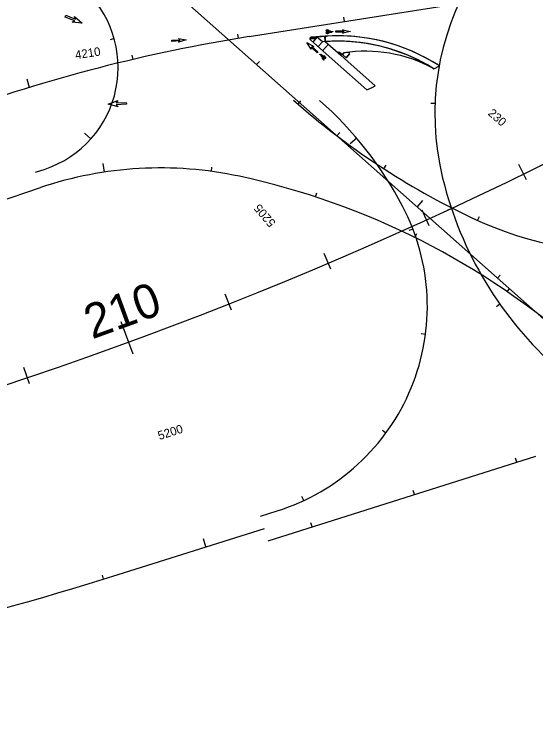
# Model space of a CAD drawing. Extents: x -5665 to 1997148, y 4 to 827579.
# Drawn here: x 1971224 to 1971710, y 802183 to 802844 of the extents above; entities that cross this region are included whole.
import ezdxf

# ---------------------------------------------------------------- set-up
doc = ezdxf.new("R2010")
doc.units = 0
for name, color, linetype in [('RD_HC_CL_Rel', 7, 'Continuous'), ('RD_HC_Data_Tic_Rel', 7, 'Continuous'), ('RD_HC_TX_Rel_Sta50', 7, 'Continuous'), ('RD_PD_SW', 7, 'Continuous'), ('RD_Sketch8', 7, 'Continuous')]:
    doc.layers.add(name, color=color, linetype=linetype)

msp = doc.modelspace()

# ---------------------------------------------------------------- linework, layer by layer
at = {"layer": 'RD_HC_CL_Rel'}
for p, q in [((1970807.31, 803367.72), (1971858, 802435.06)), ((1971443.3, 802823.09), (1971690.74, 802862.31)), ((1971244.1, 802696.62), (1971253.1, 802699.65)), ((1970599.21, 802463.58), (1971248.89, 802682.4)), ((1971460.99, 802353.28), (1971710.27, 802431.95)), ((1971453.77, 802376.17), (1971469.44, 802381.11)), ((1971321.29, 802321.77), (1971457.38, 802364.72))]:
    msp.add_line(p, q, dxfattribs=at)
for centre, radius, start, end in [((1971866.23, 802750.94), 250, 104.64509, 193.79732), ((1971221.18, 802794.42), 100, 288.61459, 48.40581), ((1971678.18, 801341.59), 1500, 99.00871, 109.98385), ((1971949.12, 803287.5), 700, 228.40581, 244.77603), ((1971276.54, 802501.92), 350, 27.78301, 48.40581), ((1970020.89, 806126.39), 3819.72, 269.57213, 296.64085), ((1971360.61, 802350.71), 350, 77.87082, 108.61459), ((1971287.07, 802008.53), 700, 48.40581, 77.87082), ((1971963.34, 802774.78), 350, 193.79732, 228.40581), ((1971799.96, 802970.88), 350, 244.77603, 302.28244), ((1971409.25, 802571.84), 200, 287.51539, 27.78301), ((1970418.4, 805182.68), 3000, 269.57213, 287.51539)]:
    msp.add_arc(centre, radius, start, end, dxfattribs=at)
at = {"layer": 'RD_HC_Data_Tic_Rel'}
for p, q in [((1971532, 802837.15), (1971531.38, 802841.1)), ((1971317.5, 802821.29), (1971313.65, 802820.21)), ((1971433.24, 802821.46), (1971432.59, 802825.4)), ((1971335.2, 802801.85), (1971334.29, 802805.75)), ((1971450.17, 802797.07), (1971452.83, 802800.06)), ((1971238.68, 802775.76), (1971236.34, 802783.41)), ((1971488.8, 802760.14), (1971491.43, 802763.16)), ((1971616.42, 802760.76), (1971612.42, 802760.92)), ((1971295.84, 802727.88), (1971289.86, 802733.21)), ((1971524.96, 802730.68), (1971527.62, 802733.68)), ((1971543.41, 802728.37), (1971537.31, 802723.2)), ((1971308.39, 802696.8), (1971307.2, 802704.71)), ((1971568.57, 802699.98), (1971570.74, 802703.34)), ((1971701.47, 802689.57), (1971694.44, 802703.94)), ((1971408.05, 802697.48), (1971408.59, 802701.45)), ((1971505.06, 802673.72), (1971506.3, 802677.52)), ((1971599.75, 802664.3), (1971605.06, 802670.28)), ((1971631.82, 802662.55), (1971628.04, 802661.27)), ((1971610.92, 802646.75), (1971604.28, 802661.3)), ((1971656.1, 802651.81), (1971657.74, 802655.45)), ((1971595.88, 802643.73), (1971592.14, 802642.3)), ((1971597.54, 802635.91), (1971599.32, 802639.49)), ((1971519.29, 802606.32), (1971513.03, 802621.04)), ((1971674.53, 802597.91), (1971677.19, 802600.91)), ((1971426.64, 802568.3), (1971420.76, 802583.18)), ((1971683.7, 802585.31), (1971685.97, 802588.61)), ((1971676.9, 802573.66), (1971673.62, 802571.37)), ((1971335.07, 802527.09), (1971324.1, 802557.15)), ((1971607.5, 802545.46), (1971603.53, 802545.98)), ((1971238.49, 802499.61), (1971233.4, 802514.78)), ((1971570.58, 802453.64), (1971567.35, 802456)), ((1971692.72, 802426.41), (1971691.51, 802430.23)), ((1971597.35, 802396.31), (1971596.15, 802400.13)), ((1971494.16, 802390.76), (1971492.46, 802394.38)), ((1971501.99, 802366.22), (1971500.79, 802370.03)), ((1971403.02, 802347.57), (1971400.61, 802355.2)), ((1971307.64, 802317.5), (1971306.46, 802321.32))]:
    msp.add_line(p, q, dxfattribs=at)
at = {"layer": 'RD_PD_SW'}
for p, q in [((1971501.22, 802822.71), (1971515.3, 802823.55)), ((1971513.89, 802823.46), (1971501.22, 802822.71)), ((1971502.72, 802817.95), (1971506.7, 802822.43)), ((1971511.42, 802818.26), (1971506.07, 802823)), ((1971514.19, 802818.47), (1971513.85, 802823.46)), ((1971514.19, 802818.47), (1971513.89, 802823.46)), ((1971513.89, 802823.46), (1971514.19, 802818.47)), ((1971514.19, 802818.47), (1971513.89, 802823.46)), ((1971500.31, 802820.09), (1971523.26, 802799.72)), ((1971500.31, 802820.09), (1971523.26, 802799.72)), ((1971507.43, 802813.77), (1971511.41, 802818.26)), ((1971517.02, 802815.96), (1971511.71, 802809.97)), ((1971517.22, 802815.78), (1971514.19, 802818.47)), ((1971514.19, 802818.47), (1971528.57, 802805.7)), ((1971514.19, 802818.47), (1971517.22, 802815.78)), ((1971526.19, 802807.81), (1971517.22, 802815.78)), ((1971517.22, 802815.78), (1971526.19, 802807.81)), ((1971531.9, 802818.74), (1971530.24, 802818.79)), ((1971526.19, 802807.81), (1971527.19, 802808.93)), ((1971527.19, 802808.93), (1971530.13, 802806.33)), ((1971531.5, 802807.87), (1971530.13, 802806.33)), ((1971530.13, 802806.33), (1971531.5, 802807.87)), ((1971536.8, 802807.09), (1971536.62, 802808.58)), ((1971528.24, 802805.33), (1971528.29, 802805.29)), ((1971530.13, 802806.33), (1971533.48, 802803.35)), ((1971536.8, 802807.09), (1971533.48, 802803.35)), ((1971533.48, 802803.35), (1971536.8, 802807.09)), ((1971522.93, 802799.35), (1971522.98, 802799.3)), ((1971523.26, 802799.72), (1971552.77, 802773.53)), ((1971523.31, 802799.68), (1971552.77, 802773.53)), ((1971615.26, 802793.14), (1971620.47, 802795.74)), ((1971614.23, 802793.58), (1971614.31, 802793.72))]:
    msp.add_line(p, q, dxfattribs=at)
msp.add_lwpolyline([(1971505.51, 802822.93), (1971500.54, 802822.52), (1971500.67, 802820.93), (1971505.64, 802821.34)], close=True, dxfattribs=at)
for points in [[(1971513.89, 802823.46), (1971513.89, 802823.46)], [(1971560.69, 802777.19), (1971535.17, 802799.85), (1971528.57, 802805.7), (1971526.19, 802807.81)], [(1971614.31, 802793.72), (1971615.26, 802793.14), (1971620.45, 802795.75), (1971619.55, 802796.34)], [(1971552.77, 802773.53), (1971557.72, 802775.82), (1971560.69, 802777.19)]]:
    msp.add_lwpolyline(points, dxfattribs=at)
for centre, radius in [((1971500.87, 802822.25), 0.146), ((1971500.91, 802821.74), 0.146), ((1971500.87, 802822.25), 0.073), ((1971500.95, 802821.25), 0.146), ((1971500.91, 802821.74), 0.073), ((1971500.95, 802821.25), 0.073), ((1971501.27, 802822.28), 0.146), ((1971501.31, 802821.78), 0.146), ((1971501.27, 802822.28), 0.073), ((1971501.35, 802821.28), 0.146), ((1971501.31, 802821.78), 0.073), ((1971501.35, 802821.28), 0.073), ((1971501.67, 802822.32), 0.146), ((1971501.71, 802821.81), 0.146), ((1971501.67, 802822.32), 0.073), ((1971501.75, 802821.31), 0.146), ((1971501.71, 802821.81), 0.073), ((1971501.75, 802821.31), 0.073), ((1971502.06, 802822.35), 0.146), ((1971502.11, 802821.84), 0.146), ((1971502.06, 802822.35), 0.073), ((1971502.15, 802821.35), 0.146), ((1971502.11, 802821.84), 0.073), ((1971502.15, 802821.35), 0.073), ((1971502.46, 802822.38), 0.146), ((1971502.5, 802821.88), 0.146), ((1971502.46, 802822.38), 0.073), ((1971502.55, 802821.38), 0.146), ((1971502.5, 802821.88), 0.073), ((1971502.55, 802821.38), 0.073), ((1971502.86, 802822.42), 0.146), ((1971502.9, 802821.91), 0.146), ((1971502.86, 802822.42), 0.073), ((1971502.94, 802821.41), 0.146), ((1971502.9, 802821.91), 0.073), ((1971502.94, 802821.41), 0.073), ((1971503.26, 802822.45), 0.146), ((1971503.3, 802821.94), 0.146), ((1971503.26, 802822.45), 0.073), ((1971503.34, 802821.44), 0.146), ((1971503.3, 802821.94), 0.073), ((1971503.34, 802821.44), 0.073), ((1971503.66, 802822.48), 0.146), ((1971503.7, 802821.97), 0.146), ((1971503.66, 802822.48), 0.073), ((1971503.74, 802821.48), 0.146), ((1971503.7, 802821.97), 0.073), ((1971503.74, 802821.48), 0.073), ((1971504.06, 802822.51), 0.146), ((1971504.1, 802822.01), 0.146), ((1971504.06, 802822.51), 0.073), ((1971504.14, 802821.51), 0.146), ((1971504.1, 802822.01), 0.073), ((1971504.14, 802821.51), 0.073), ((1971504.46, 802822.55), 0.146), ((1971504.5, 802822.04), 0.146), ((1971504.46, 802822.55), 0.073), ((1971504.54, 802821.54), 0.146), ((1971504.5, 802822.04), 0.073), ((1971504.54, 802821.54), 0.073), ((1971504.86, 802822.58), 0.146), ((1971504.9, 802822.07), 0.146), ((1971504.86, 802822.58), 0.073), ((1971504.94, 802821.58), 0.146), ((1971504.9, 802822.07), 0.073), ((1971504.94, 802821.58), 0.073), ((1971505.25, 802822.61), 0.146), ((1971505.3, 802822.11), 0.146), ((1971505.25, 802822.61), 0.073), ((1971505.34, 802821.61), 0.146), ((1971505.3, 802822.11), 0.073), ((1971505.34, 802821.61), 0.073)]:
    msp.add_circle(centre, radius, dxfattribs=at)
for centre, radius, start, end in [((1971501.31, 802821.21), 1.5, 93.40581, 228.40581), ((1971501.31, 802821.21), 1.5, 93.40581, 228.40581), ((1971525.64, 802649.86), 174, 56.97514, 95.44839), ((1971525.64, 802649.86), 174, 57.33665, 93.87004), ((1971525.63, 802649.82), 169.04, 57.9779, 94.8263), ((1971525.64, 802649.86), 169, 58.35128, 93.88378), ((1971525.64, 802649.86), 169, 88.43947, 93.88378), ((1971525.64, 802649.86), 169, 58.35128, 87.87679), ((1971551.92, 802679.49), 130, 61.36, 99.03754), ((1971551.92, 802679.49), 130, 96.75765, 99.03754)]:
    msp.add_arc(centre, radius, start, end, dxfattribs=at)
at = {"layer": 'RD_Sketch8'}
for p, q in [((1971271.8, 802841.31), (1971272.49, 802842.98)), ((1971280.69, 802837.67), (1971271.8, 802841.31)), ((1971272.49, 802842.98), (1971281.37, 802839.33)), ((1971280.59, 802841.86), (1971287.8, 802835.72)), ((1971281.37, 802839.33), (1971280.59, 802841.86)), ((1971278.36, 802836.42), (1971280.69, 802837.67)), ((1971287.8, 802835.72), (1971278.36, 802836.42)), ((1971516, 802828.23), (1971516.01, 802828.47)), ((1971516.01, 802828.47), (1971516.01, 802828.23)), ((1971516.01, 802828.23), (1971516.01, 802828.47)), ((1971516.05, 802829.4), (1971516.04, 802829.16)), ((1971516.04, 802829.16), (1971516.05, 802829.4)), ((1971523.99, 802828.37), (1971531.67, 802828.38)), ((1971523.99, 802827.33), (1971523.99, 802828.37)), ((1971537.52, 802827.87), (1971530.32, 802826.16)), ((1971530.33, 802829.55), (1971537.52, 802827.87)), ((1971531.67, 802828.38), (1971530.33, 802829.55)), ((1971377.34, 802821.28), (1971384.63, 802820.05)), ((1971378.76, 802820.19), (1971377.34, 802821.28)), ((1971515.9, 802826.07), (1971515.91, 802826.3)), ((1971515.92, 802826.3), (1971515.91, 802826.07)), ((1971515.91, 802826.07), (1971515.92, 802826.3)), ((1971515.95, 802827.23), (1971515.94, 802826.99)), ((1971515.94, 802826.99), (1971515.95, 802827.23)), ((1971531.67, 802827.34), (1971523.99, 802827.33)), ((1971530.32, 802826.16), (1971531.67, 802827.34)), ((1971371.09, 802819.69), (1971378.76, 802820.19)), ((1971371.16, 802818.66), (1971371.09, 802819.69)), ((1971378.82, 802819.16), (1971371.16, 802818.66)), ((1971384.63, 802820.05), (1971377.55, 802817.9)), ((1971377.55, 802817.9), (1971378.82, 802819.16)), ((1971501.08, 802811.45), (1971496.86, 802817.52)), ((1971496.86, 802817.52), (1971503.35, 802813.96)), ((1971506.58, 802808.08), (1971500.87, 802813.22)), ((1971500.87, 802813.22), (1971501.08, 802811.45)), ((1971503.35, 802813.96), (1971501.56, 802813.99)), ((1971501.56, 802813.99), (1971507.27, 802808.85)), ((1971507.27, 802808.85), (1971506.58, 802808.08)), ((1971511.95, 802802.18), (1971511.78, 802802)), ((1971511.79, 802802), (1971511.95, 802802.17)), ((1971512.43, 802802.67), (1971512.6, 802802.84)), ((1971512.6, 802802.84), (1971512.43, 802802.67)), ((1971512.6, 802802.84), (1971512.44, 802802.67)), ((1971513.31, 802803.55), (1971513.48, 802803.72)), ((1971513.48, 802803.72), (1971513.31, 802803.55)), ((1971514.12, 802804.38), (1971513.96, 802804.21)), ((1971513.96, 802804.21), (1971514.12, 802804.38)), ((1971514.12, 802804.38), (1971513.96, 802804.21)), ((1971311.93, 802760.1), (1971320.78, 802763.47)), ((1971320.78, 802763.47), (1971319.2, 802761.35)), ((1971319.2, 802761.35), (1971328.79, 802761.82)), ((1971328.79, 802761.82), (1971328.88, 802760.02)), ((1971321.06, 802757.6), (1971311.93, 802760.1)), ((1971328.88, 802760.02), (1971319.29, 802759.56)), ((1971319.29, 802759.56), (1971321.06, 802757.6))]:
    msp.add_line(p, q, dxfattribs=at)
for points in [[(1971520.29, 802827.39), (1971519.64, 802827.92), (1971518.66, 802828.29), (1971518.32, 802828.14), (1971519.3, 802827.76), (1971518.32, 802827.55), (1971517.99, 802828.15), (1971516.68, 802828.04), (1971516.96, 802827.72), (1971517.64, 802827.75), (1971517.93, 802827.39), (1971515.64, 802828.02), (1971515.34, 802827.75), (1971518.25, 802826.92)], [(1971521.03, 802827.86), (1971521.05, 802827.81), (1971521.06, 802827.77), (1971521.07, 802827.74), (1971521.08, 802827.72), (1971521.08, 802827.69), (1971521.08, 802827.67), (1971521.07, 802827.64), (1971521.06, 802827.61), (1971521.05, 802827.6), (1971521.03, 802827.55), (1971521.01, 802827.53), (1971520.35, 802827.56), (1971520.33, 802827.6), (1971520.32, 802827.63), (1971520.31, 802827.68), (1971520.3, 802827.72), (1971520.31, 802827.77), (1971520.32, 802827.81), (1971520.34, 802827.84), (1971520.35, 802827.87), (1971520.36, 802827.89)], [(1971509.12, 802806.47), (1971509.13, 802806.53), (1971509.15, 802806.57), (1971509.16, 802806.6), (1971509.18, 802806.62), (1971509.2, 802806.64), (1971509.21, 802806.65), (1971509.23, 802806.67), (1971509.26, 802806.68), (1971509.28, 802806.69), (1971509.32, 802806.71), (1971509.35, 802806.71), (1971509.83, 802806.25), (1971509.81, 802806.21), (1971509.8, 802806.17), (1971509.77, 802806.13), (1971509.75, 802806.09), (1971509.71, 802806.07), (1971509.67, 802806.04), (1971509.64, 802806.03), (1971509.61, 802806.02), (1971509.59, 802806.01)], [(1971509.98, 802806.33), (1971510.11, 802805.51), (1971510.59, 802804.57), (1971510.94, 802804.46), (1971510.47, 802805.4), (1971511.34, 802804.9), (1971511.18, 802804.22), (1971512.23, 802803.44), (1971512.23, 802803.86), (1971511.71, 802804.29), (1971511.74, 802804.75), (1971513.01, 802802.76), (1971513.41, 802802.75), (1971511.81, 802805.31)]]:
    msp.add_lwpolyline(points, close=True, dxfattribs=at)
for centre, major_axis, ratio, start_param, end_param in [((1971516.05, 802828.81), (-1.38, 0.06), 0.421657, 0.002013, 1.556277), ((1971516.05, 802828.81), (-1.38, 0.06), 0.421657, 4.73092, 6.285191), ((1971516.02, 802828.81), (-1.05, 0.04), 0.327603, 4.968366, 6.281137), ((1971516.02, 802828.81), (-1.05, 0.04), 0.327603, 6.281144, 7.855553), ((1971516.02, 802828.81), (-1.05, 0.04), 0.327603, 4.706721, 4.968366), ((1971516.02, 802828.81), (-1.05, 0.04), 0.327603, 1.575, 3.139545), ((1971516.05, 802828.81), (-1.38, 0.06), 0.421657, 1.55828, 3.143599), ((1971516.02, 802828.81), (-1.05, 0.04), 0.327603, 3.139551, 4.704089), ((1971516.05, 802828.81), (-1.38, 0.06), 0.421657, 3.205785, 4.728917), ((1971516.05, 802828.81), (-1.38, 0.06), 0.421657, 3.143612, 3.205785), ((1971515.95, 802826.65), (-1.38, 0.06), 0.421657, 0.002013, 1.556277), ((1971515.95, 802826.65), (-1.38, 0.06), 0.421657, 4.73092, 6.285191), ((1971515.92, 802826.65), (-1.05, 0.04), 0.327603, 4.968366, 6.281137), ((1971515.92, 802826.65), (-1.05, 0.04), 0.327603, 6.281144, 7.855553), ((1971515.92, 802826.65), (-1.05, 0.04), 0.327603, 4.706721, 4.968366), ((1971515.95, 802826.65), (-1.38, 0.06), 0.421657, 1.55828, 3.143599), ((1971515.92, 802826.65), (-1.05, 0.04), 0.327603, 1.575, 3.139545), ((1971515.92, 802826.65), (-1.05, 0.04), 0.327603, 3.139551, 4.704089), ((1971515.95, 802826.65), (-1.38, 0.06), 0.421657, 3.205785, 4.728917), ((1971515.95, 802826.65), (-1.38, 0.06), 0.421657, 3.143612, 3.205785), ((1971512.18, 802802.44), (0.984, -0.971), 0.421657, 3.205785, 4.728917), ((1971512.18, 802802.44), (0.984, -0.971), 0.421657, 3.143612, 3.205785), ((1971512.18, 802802.44), (0.984, -0.971), 0.421657, 1.55828, 3.143599), ((1971512.2, 802802.42), (0.757, -0.73), 0.327603, 3.139551, 4.704089), ((1971512.2, 802802.42), (0.757, -0.73), 0.327603, 1.575, 3.139545), ((1971512.18, 802802.44), (0.984, -0.971), 0.421657, 4.73092, 6.285191), ((1971512.2, 802802.42), (0.757, -0.73), 0.327603, 4.706721, 4.968366), ((1971512.2, 802802.42), (0.757, -0.73), 0.327603, 4.968366, 6.281137), ((1971512.2, 802802.42), (0.757, -0.73), 0.327603, 6.281144, 7.855553), ((1971513.7, 802803.98), (0.984, -0.971), 0.421657, 3.205785, 4.728917), ((1971512.18, 802802.44), (0.984, -0.971), 0.421657, 0.002013, 1.556277), ((1971513.7, 802803.98), (0.984, -0.971), 0.421657, 3.143612, 3.205785), ((1971513.7, 802803.98), (0.984, -0.971), 0.421657, 1.55828, 3.143599), ((1971513.72, 802803.96), (0.757, -0.73), 0.327603, 3.139551, 4.704089), ((1971513.72, 802803.96), (0.757, -0.73), 0.327603, 1.575, 3.139545), ((1971513.7, 802803.98), (0.984, -0.971), 0.421657, 4.73092, 6.285191), ((1971513.72, 802803.96), (0.757, -0.73), 0.327603, 4.706721, 4.968366), ((1971513.72, 802803.96), (0.757, -0.73), 0.327603, 4.968366, 6.281137), ((1971513.72, 802803.96), (0.757, -0.73), 0.327603, 6.281144, 7.855553), ((1971513.7, 802803.98), (0.984, -0.971), 0.421657, 0.002013, 1.556277)]:
    msp.add_ellipse(centre, major_axis=major_axis, ratio=ratio, start_param=start_param, end_param=end_param, dxfattribs=at)

# ---------------------------------------------------------------- texts
at = {"layer": 'RD_HC_TX_Rel_Sta50'}
for s, height, rotation, p in [('4210', 8, 8.5811, (1971281.7, 802801.99)), ('230', 8, 318.40581, (1971665.08, 802750.72)), ('5205', 8, 130.31588, (1971468.43, 802649.81)), ('210', 32, 20.05816, (1971296.85, 802540.81)), ('5200', 8, 17.51539, (1971359.63, 802447.12))]:
    msp.add_text(s, height=height, rotation=rotation, dxfattribs=at).set_placement(p)

doc.saveas('drawing.dxf')
